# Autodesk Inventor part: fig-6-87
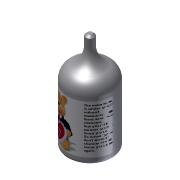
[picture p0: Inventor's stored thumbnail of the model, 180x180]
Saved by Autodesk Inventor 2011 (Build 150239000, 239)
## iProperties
Shininess: 64.0
Length Units: 11269
Angle Units: 11279
Time Units: 11290
Mass Units: 11283
Length Display Precision: 3
Angle Display Precision: 2
Compacted: True
Part Number: fig-6-87
Document SubType Name: Modeling
Created: 2002-12
Designer: deepak
Density: 1 g/cm^3
Density: 0.0
Volumn: 0.0
Area: 0.0
PropertySet Name: Model Information
Control State: 0
Master: False
Checked Out: False
Author: deepak
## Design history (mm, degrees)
node "Sketch1"
sketch "Sketch2"
  geometry: L1 (2.054, 26.655)-(2.054, 21.177); L2 (11.64, 6.114)-(11.64, -24.209); L3 (11.64, -24.209)-(-0.098, -24.209); L4 (-0.098, -24.209)-(-0.098, 26.655); L5 (-0.098, 26.655)-(2.054, 26.655); A1 r 9.502 centre (11.556, 21.177) between (2.054, 21.177) and (7.532, 12.57); A2 r 7.127 centre (4.514, 6.114) between (11.64, 6.114) and (7.532, 12.57)
  constraints: 10 end point, 4 point on circle, 3 parallel, 3 tangent, 2 centre point, 1 perpendicular, 1 vertical
revolve "Revolution1" sketch "Sketch2" stored, may be unused: angle "d0" = 90 deg
fillet "Fillet1" dims "d1" = 2
chamfer "Chamfer1" distance "d2" = 1; stored, may be unused: second distance "d3" = 2, angle "d21" = 45 deg
workplane "Work Plane1"
workplane "Work Plane2"
sketch "Sketch3"
  geometry: L1 (-18.179, 13.331)-(17.364, 13.331); L2 (17.364, 13.331)-(17.364, -11.702); L3 (17.364, -11.702)-(-18.179, -11.702); L4 (-18.179, -11.702)-(-18.179, 13.331); 1 other entity
  constraints: 2 other
feature "Decal3" sketch "Sketch3"
body "Solid1"
node "Image2"
other parameters: "d4" = -8
